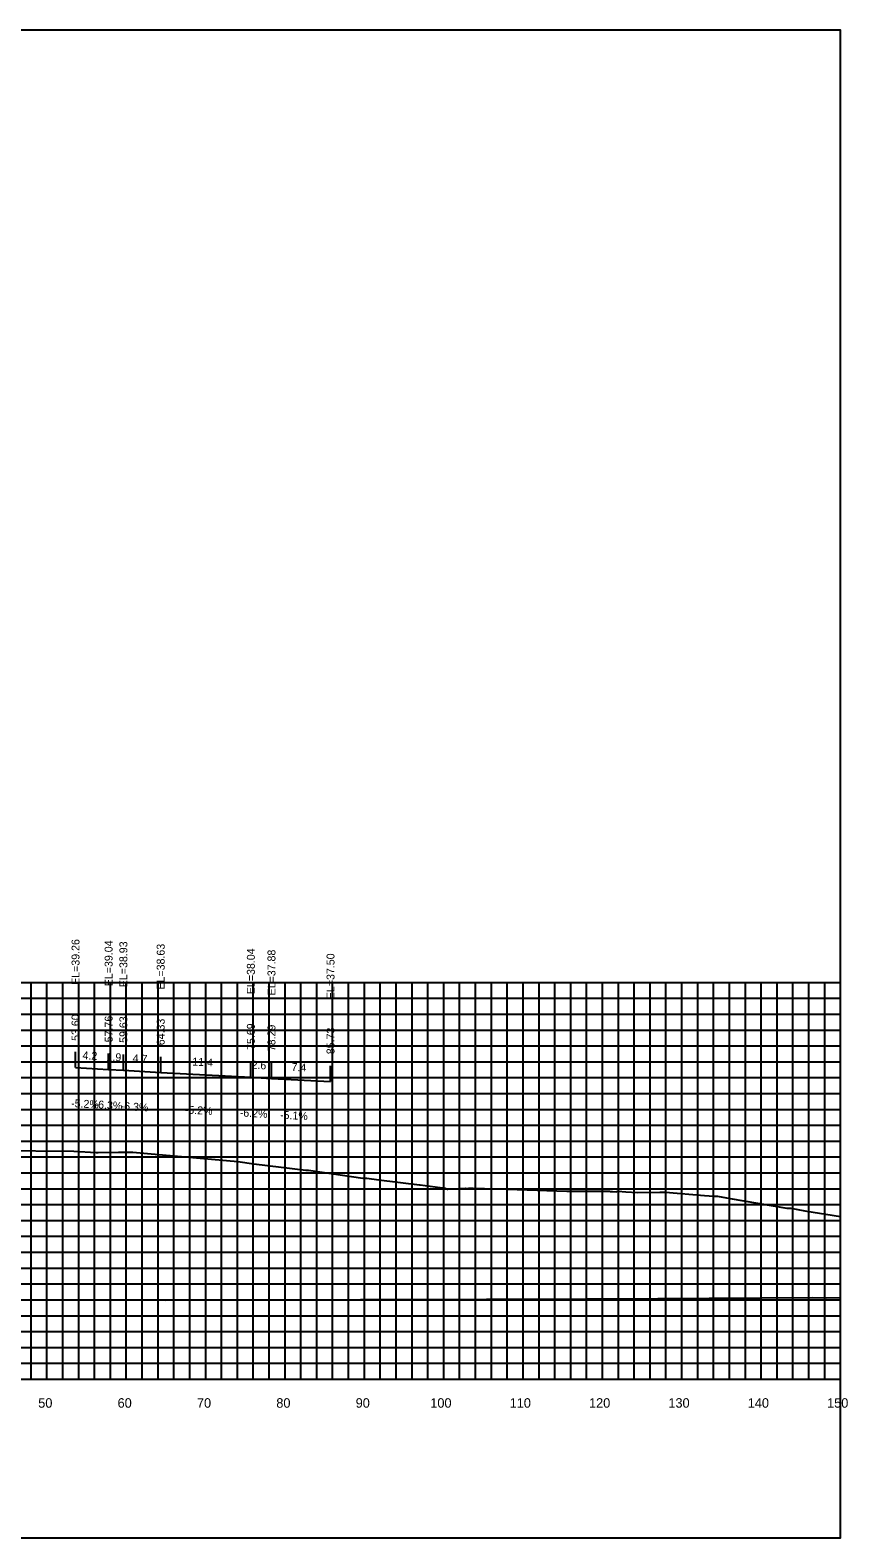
# Model space of a CAD drawing. Extents: x 1800880 to 1818864, y 245271 to 250560.
# Drawn here: x 1811165.9 to 1811269, y 247840 to 248030 of the extents above; entities that cross this region are included whole.
import ezdxf

# ---------------------------------------------------------------- set-up
doc = ezdxf.new("R2010")
doc.units = 0
for name, color, linetype in [('ANNO-TXT', 7, 'Continuous'), ('CL-CNST', 7, 'Continuous'), ('DESIGN - DRAINAGE - Bridges', 7, 'Continuous'), ('Level 37', 7, 'Continuous'), ('Level 46', 7, 'Continuous'), ('Level 62', 7, 'Continuous'), ('SHT-BDR', 7, 'Continuous')]:
    doc.layers.add(name, color=color, linetype=linetype)

msp = doc.modelspace()

# ---------------------------------------------------------------- linework, layer by layer
at = {"layer": 'CL-CNST'}
msp.add_lwpolyline([(1811161.8, 247888.8), (1811171.45, 247888.71), (1811174.24, 247888.55), (1811174.51, 247888.54), (1811177.09, 247888.58), (1811178.39, 247888.6), (1811178.45, 247888.6), (1811178.8, 247888.6), (1811178.9, 247888.6), (1811180.74, 247888.43), (1811192.1, 247887.43), (1811194.12, 247887.14), (1811200.66, 247886.34), (1811201.02, 247886.33), (1811207.86, 247885.33), (1811208.13, 247885.33), (1811208.35, 247885.33), (1811209.88, 247885.1), (1811215.01, 247884.49), (1811215.09, 247884.48), (1811218.22, 247884.06), (1811218.52, 247883.95), (1811218.58, 247883.95), (1811220.74, 247884.06), (1811220.98, 247884.02), (1811221.22, 247884.07), (1811221.22, 247884.07), (1811221.22, 247884.07), (1811221.22, 247884.07), (1811221.23, 247884.07), (1811221.23, 247884.07), (1811221.23, 247884.07), (1811221.24, 247884.07), (1811221.24, 247884.07), (1811221.25, 247884.07), (1811221.25, 247884.07), (1811221.26, 247884.07), (1811221.27, 247884.07), (1811221.27, 247884.07), (1811221.28, 247884.07), (1811221.29, 247884.07), (1811221.3, 247884.07), (1811221.31, 247884.07), (1811221.33, 247884.07), (1811221.34, 247884.07), (1811221.36, 247884.07), (1811221.38, 247884.07), (1811221.4, 247884.07), (1811221.43, 247884.07), (1811221.46, 247884.07), (1811221.5, 247884.07), (1811221.55, 247884.07), (1811221.62, 247884.07), (1811221.72, 247884.07), (1811221.75, 247884.07), (1811226.05, 247883.94), (1811233.55, 247883.7), (1811236.24, 247883.69), (1811237.19, 247883.69), (1811237.3, 247883.69), (1811238.11, 247883.7), (1811238.28, 247883.69), (1811238.52, 247883.68), (1811238.68, 247883.67), (1811238.81, 247883.67), (1811238.9, 247883.66), (1811238.98, 247883.66), (1811239.04, 247883.65), (1811239.1, 247883.65), (1811239.14, 247883.65), (1811239.18, 247883.65), (1811239.21, 247883.65), (1811239.24, 247883.65), (1811239.26, 247883.64), (1811239.29, 247883.64), (1811239.31, 247883.64), (1811239.83, 247883.61), (1811239.86, 247883.64), (1811240.02, 247883.66), (1811240.99, 247883.58), (1811242.45, 247883.52), (1811245.28, 247883.56), (1811245.51, 247883.55), (1811245.53, 247883.55), (1811245.93, 247883.55), (1811246.01, 247883.55), (1811250.92, 247883.13), (1811252.07, 247883.03), (1811252.18, 247883.03), (1811252.42, 247883.03), (1811252.57, 247883.03), (1811254.13, 247882.77), (1811261.29, 247881.52), (1811261.35, 247881.52), (1811261.78, 247881.53), (1811263.56, 247881.2), (1811268.06, 247880.48)], dxfattribs=at)
at = {"layer": 'DESIGN - DRAINAGE - Bridges'}
for p, q in [((1811268.06, 247859.99), (1811268.06, 247909.99)), ((1811268.12, 247909.99), (1811268.06, 247909.99)), ((1811268.12, 247899.99), (1811268.06, 247899.99)), ((1811268.12, 247889.99), (1811268.06, 247889.99)), ((1811268.12, 247879.99), (1811268.06, 247879.99)), ((1811268.12, 247869.99), (1811268.06, 247869.99)), ((1810968.06, 247859.99), (1811268.06, 247859.99)), ((1811168.06, 247859.93), (1811168.06, 247859.99)), ((1811178.06, 247859.93), (1811178.06, 247859.99)), ((1811188.06, 247859.93), (1811188.06, 247859.99)), ((1811198.06, 247859.93), (1811198.06, 247859.99)), ((1811208.06, 247859.93), (1811208.06, 247859.99)), ((1811218.06, 247859.93), (1811218.06, 247859.99)), ((1811228.06, 247859.93), (1811228.06, 247859.99)), ((1811238.06, 247859.93), (1811238.06, 247859.99)), ((1811248.06, 247859.93), (1811248.06, 247859.99)), ((1811258.06, 247859.93), (1811258.06, 247859.99)), ((1811268.06, 247859.93), (1811268.06, 247859.99)), ((1811268.12, 247859.99), (1811268.06, 247859.99))]:
    msp.add_line(p, q, dxfattribs=at)
at = {"layer": 'Level 37'}
for p, q in [((1811171.66, 247899.25), (1811171.66, 247901.25)), ((1811175.83, 247899.03), (1811175.83, 247901.03)), ((1811177.69, 247898.92), (1811177.69, 247900.92)), ((1811182.39, 247898.62), (1811182.39, 247900.62)), ((1811193.75, 247898.03), (1811193.75, 247900.03)), ((1811196.35, 247897.87), (1811196.35, 247899.87)), ((1811203.79, 247897.49), (1811203.79, 247899.49))]:
    msp.add_line(p, q, dxfattribs=at)
msp.add_lwpolyline([(1810968.06, 247839.99), (1811268.06, 247839.99), (1811268.06, 248029.99), (1810968.06, 248029.99)], close=True, dxfattribs=at)
at = {"layer": 'Level 46'}
for p, q in [((1810968.06, 247909.99), (1811268.06, 247909.99)), ((1811166.06, 247859.99), (1811166.06, 247909.99)), ((1811168.06, 247859.99), (1811168.06, 247909.99)), ((1811170.06, 247859.99), (1811170.06, 247909.99)), ((1811172.06, 247859.99), (1811172.06, 247909.99)), ((1811174.06, 247859.99), (1811174.06, 247909.99)), ((1811176.06, 247859.99), (1811176.06, 247909.99)), ((1811178.06, 247859.99), (1811178.06, 247909.99)), ((1811180.06, 247859.99), (1811180.06, 247909.99)), ((1811182.06, 247859.99), (1811182.06, 247909.99)), ((1811184.06, 247859.99), (1811184.06, 247909.99)), ((1811186.06, 247859.99), (1811186.06, 247909.99)), ((1811188.06, 247859.99), (1811188.06, 247909.99)), ((1811190.06, 247859.99), (1811190.06, 247909.99)), ((1811192.06, 247859.99), (1811192.06, 247909.99)), ((1811194.06, 247859.99), (1811194.06, 247909.99)), ((1811196.06, 247859.99), (1811196.06, 247909.99)), ((1811198.06, 247859.99), (1811198.06, 247909.99)), ((1811200.06, 247859.99), (1811200.06, 247909.99)), ((1811202.06, 247859.99), (1811202.06, 247909.99)), ((1811204.06, 247859.99), (1811204.06, 247909.99)), ((1811206.06, 247859.99), (1811206.06, 247909.99)), ((1811208.06, 247859.99), (1811208.06, 247909.99)), ((1811210.06, 247859.99), (1811210.06, 247909.99)), ((1811212.06, 247859.99), (1811212.06, 247909.99)), ((1811214.06, 247859.99), (1811214.06, 247909.99)), ((1811216.06, 247859.99), (1811216.06, 247909.99)), ((1811218.06, 247859.99), (1811218.06, 247909.99)), ((1811220.06, 247859.99), (1811220.06, 247909.99)), ((1811222.06, 247859.99), (1811222.06, 247909.99)), ((1811224.06, 247859.99), (1811224.06, 247909.99)), ((1811226.06, 247859.99), (1811226.06, 247909.99)), ((1811228.06, 247859.99), (1811228.06, 247909.99)), ((1811230.06, 247859.99), (1811230.06, 247909.99)), ((1811232.06, 247859.99), (1811232.06, 247909.99)), ((1811234.06, 247859.99), (1811234.06, 247909.99)), ((1811236.06, 247859.99), (1811236.06, 247909.99)), ((1811238.06, 247859.99), (1811238.06, 247909.99)), ((1811240.06, 247859.99), (1811240.06, 247909.99)), ((1811242.06, 247859.99), (1811242.06, 247909.99)), ((1811244.06, 247859.99), (1811244.06, 247909.99)), ((1811246.06, 247859.99), (1811246.06, 247909.99)), ((1811248.06, 247859.99), (1811248.06, 247909.99)), ((1811250.06, 247859.99), (1811250.06, 247909.99)), ((1811252.06, 247859.99), (1811252.06, 247909.99)), ((1811254.06, 247859.99), (1811254.06, 247909.99)), ((1811256.06, 247859.99), (1811256.06, 247909.99)), ((1811258.06, 247859.99), (1811258.06, 247909.99)), ((1811260.06, 247859.99), (1811260.06, 247909.99)), ((1811262.06, 247859.99), (1811262.06, 247909.99)), ((1811264.06, 247859.99), (1811264.06, 247909.99)), ((1811266.06, 247859.99), (1811266.06, 247909.99)), ((1811268.06, 247859.99), (1811268.06, 247909.99)), ((1810968.06, 247907.99), (1811268.06, 247907.99)), ((1810968.06, 247905.99), (1811268.06, 247905.99)), ((1810968.06, 247903.99), (1811268.06, 247903.99)), ((1810968.06, 247901.99), (1811268.06, 247901.99)), ((1810968.06, 247899.99), (1811268.06, 247899.99)), ((1810968.06, 247897.99), (1811268.06, 247897.99)), ((1810968.06, 247895.99), (1811268.06, 247895.99)), ((1810968.06, 247893.99), (1811268.06, 247893.99)), ((1810968.06, 247891.99), (1811268.06, 247891.99)), ((1810968.06, 247889.99), (1811268.06, 247889.99)), ((1810968.06, 247887.99), (1811268.06, 247887.99)), ((1810968.06, 247885.99), (1811268.06, 247885.99)), ((1810968.06, 247883.99), (1811268.06, 247883.99)), ((1810968.06, 247881.99), (1811268.06, 247881.99)), ((1810968.06, 247879.99), (1811268.06, 247879.99)), ((1810968.06, 247877.99), (1811268.06, 247877.99)), ((1810968.06, 247875.99), (1811268.06, 247875.99)), ((1810968.06, 247873.99), (1811268.06, 247873.99)), ((1810968.06, 247871.99), (1811268.06, 247871.99)), ((1810968.06, 247869.99), (1811268.06, 247869.99)), ((1810968.06, 247867.99), (1811268.06, 247867.99)), ((1810968.06, 247865.99), (1811268.06, 247865.99)), ((1810968.06, 247863.99), (1811268.06, 247863.99)), ((1810968.06, 247861.99), (1811268.06, 247861.99)), ((1810968.06, 247859.99), (1811268.06, 247859.99))]:
    msp.add_line(p, q, dxfattribs=at)
at = {"layer": 'Level 62'}
for points in [[(1811171.66, 247899.25), (1811175.83, 247899.03), (1811177.69, 247898.92), (1811182.39, 247898.62), (1811193.75, 247898.03), (1811196.35, 247897.87), (1811203.79, 247897.49)], [(1810968.06, 247871.33), (1810988.71, 247870.86), (1811000.23, 247870.77), (1811016.47, 247870.57), (1811031.54, 247870.47), (1811044.22, 247870.35), (1811061.92, 247870.26), (1811071.98, 247870.19), (1811091.69, 247870.12), (1811099.73, 247870.05), (1811121.03, 247870.01), (1811127.49, 247869.97), (1811150.08, 247869.97), (1811155.25, 247869.93), (1811178.9, 247869.97), (1811183, 247869.94), (1811207.56, 247870.02), (1811210.76, 247870.01), (1811236.08, 247870.13), (1811238.51, 247870.13), (1811264.5, 247870.28), (1811266.27, 247870.24), (1811268.06, 247870.26)]]:
    msp.add_lwpolyline(points, dxfattribs=at)

# ---------------------------------------------------------------- texts
for s, p in [('50', (1811166.96, 247856.39)), ('60', (1811176.96, 247856.39)), ('70', (1811186.96, 247856.39)), ('80', (1811196.96, 247856.39)), ('90', (1811206.96, 247856.39)), ('100', (1811216.36, 247856.39)), ('110', (1811226.36, 247856.39)), ('120', (1811236.36, 247856.39)), ('130', (1811246.36, 247856.39)), ('140', (1811256.36, 247856.39)), ('150', (1811266.36, 247856.39))]:
    msp.add_text(s, height=1.2).set_placement(p)
at = {"layer": 'ANNO-TXT'}
for s, rotation, p in [('4.2', 357.0072, (1811172.52, 247900.31)), ('1.9', 356.4036, (1811175.54, 247900.15)), ('4.7', 356.4036, (1811178.83, 247899.95)), ('11.4', 357.0406, (1811186.35, 247899.52)), ('2.6', 356.4278, (1811193.81, 247899.13)), ('7.4', 357.0558, (1811198.85, 247898.85)), ('-5.2%', 357.0072, (1811171.08, 247894.28)), ('-6.3%', 356.4036, (1811174.04, 247894.14)), ('-6.3%', 356.4036, (1811177.32, 247893.93)), ('-5.2%', 357.0406, (1811185.41, 247893.46)), ('-6.2%', 356.4278, (1811192.33, 247893.11)), ('-5.1%', 357.0558, (1811197.41, 247892.81))]:
    msp.add_text(s, height=1, rotation=rotation, dxfattribs=at).set_placement(p)
at = {"layer": 'SHT-BDR'}
for s, p in [('EL=39.26', (1811172.16, 247909.68)), ('EL=39.04', (1811176.33, 247909.51)), ('EL=38.93', (1811178.19, 247909.39)), ('EL=38.63', (1811182.89, 247909.09)), ('EL=38.04', (1811194.25, 247908.51)), ('EL=37.88', (1811196.85, 247908.35)), ('EL=37.50', (1811204.29, 247907.88)), ('53.60', (1811172.16, 247902.62)), ('57.76', (1811176.33, 247902.44)), ('59.63', (1811178.19, 247902.37)), ('64.33', (1811182.89, 247902.07)), ('75.69', (1811194.25, 247901.48)), ('78.29', (1811196.85, 247901.32)), ('85.73', (1811204.29, 247900.94))]:
    msp.add_text(s, height=1, rotation=90, dxfattribs=at).set_placement(p)

doc.saveas('drawing.dxf')
